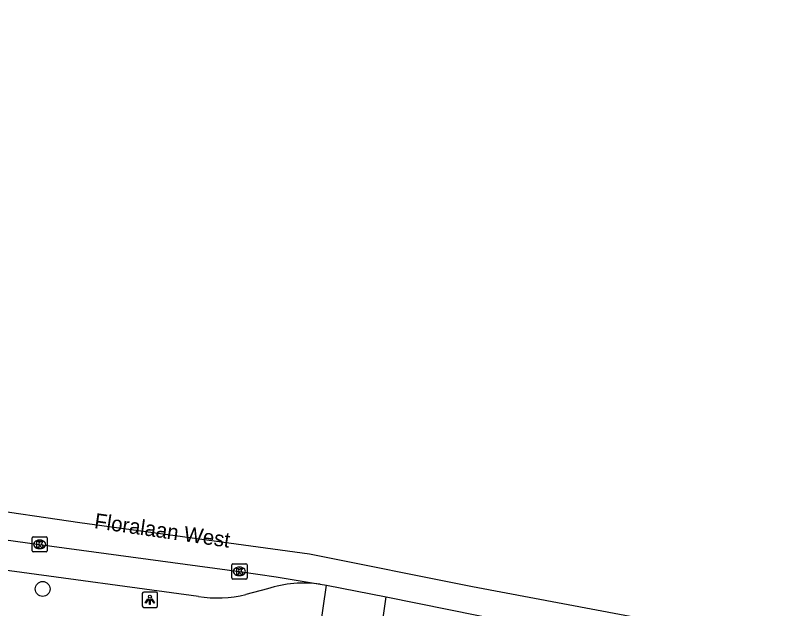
# Model space of a CAD drawing. Extents: x 161486 to 162249, y 379484 to 380829.
# Drawn here: x 162088.8 to 162140, y 380768.6 to 380807.6 of the extents above; entities that cross this region are included whole.
import ezdxf

# ---------------------------------------------------------------- set-up
doc = ezdxf.new("R2010")
doc.units = 0
for name, color, linetype in [('IMGEO_Boom', 7, 'Continuous'), ('IMGEO_Fietspad_open', 7, 'Continuous'), ('IMGEO_Kolk', 7, 'Continuous'), ('IMGEO_Lichtpunt', 7, 'Continuous'), ('IMGEO_Openbare_ruimte_label', 7, 'Continuous'), ('IMGEO_Rijbaan_lokaal_gesloten', 7, 'Continuous'), ('IMGEO_Voetpad_open', 7, 'Continuous')]:
    doc.layers.add(name, color=color, linetype=linetype)

msp = doc.modelspace()

# ---------------------------------------------------------------- linework, layer by layer
at = {"layer": 'IMGEO_Boom'}
msp.add_circle((162090.611, 380769.898), 0.489, dxfattribs=at)
at = {"layer": 'IMGEO_Fietspad_open'}
for points in [[(162082, 380773.982), (162090.414, 380772.833), (162103.563, 380771.053), (162105.995, 380770.702), (162108.893, 380770.206)], [(162108.893, 380770.206), (162109.295, 380770.138)], [(162109.295, 380770.138), (162113.227, 380769.38)], [(162113.227, 380769.38), (162121.37, 380767.728), (162122.685, 380767.488)]]:
    msp.add_lwpolyline(points, dxfattribs=at)
at = {"layer": 'IMGEO_Kolk'}
for p, q in [((162089.917, 380772.406), (162089.917, 380773.258)), ((162089.992, 380773.332), (162090.844, 380773.332)), ((162090.405, 380773.112), (162090.43, 380773.112)), ((162090.918, 380773.258), (162090.918, 380772.406)), ((162090.428, 380772.552), (162090.403, 380772.552)), ((162090.844, 380772.332), (162089.992, 380772.332)), ((162103.066, 380770.626), (162103.066, 380771.478)), ((162103.141, 380771.552), (162103.993, 380771.552)), ((162104.067, 380771.478), (162104.067, 380770.626)), ((162103.554, 380771.332), (162103.579, 380771.332)), ((162103.993, 380770.552), (162103.141, 380770.552)), ((162103.577, 380770.772), (162103.552, 380770.772))]:
    msp.add_line(p, q, dxfattribs=at)
for points in [[(162089.917, 380772.406), (162089.917, 380773.258)], [(162089.992, 380773.332), (162090.844, 380773.332)], [(162090.238, 380773.032), (162090.361, 380773.032), (162090.361, 380772.881), (162090.491, 380773.032), (162090.655, 380773.032), (162090.509, 380772.881), (162090.662, 380772.632), (162090.51, 380772.632), (162090.425, 380772.796), (162090.361, 380772.729), (162090.361, 380772.632), (162090.238, 380772.632), (162090.238, 380773.032)], [(162090.918, 380773.258), (162090.918, 380772.406)], [(162090.844, 380772.332), (162089.992, 380772.332)], [(162103.066, 380770.626), (162103.066, 380771.478)], [(162103.141, 380771.552), (162103.993, 380771.552)], [(162104.067, 380771.478), (162104.067, 380770.626)], [(162103.387, 380771.252), (162103.51, 380771.252), (162103.51, 380771.101), (162103.64, 380771.252), (162103.804, 380771.252), (162103.658, 380771.101), (162103.811, 380770.852), (162103.659, 380770.852), (162103.574, 380771.016), (162103.51, 380770.949), (162103.51, 380770.852), (162103.387, 380770.852), (162103.387, 380771.252)], [(162103.993, 380770.552), (162103.141, 380770.552)]]:
    msp.add_lwpolyline(points, dxfattribs=at)
for centre, start, end in [((162089.994, 380773.256), 91.552, 178.448), ((162089.994, 380773.256), 91.552, 178.448), ((162090.842, 380773.256), 1.552, 88.448), ((162090.842, 380773.256), 1.552, 88.448), ((162089.994, 380772.408), 181.552, 268.448), ((162089.994, 380772.408), 181.552, 268.448), ((162090.842, 380772.408), 271.552, 358.448), ((162090.842, 380772.408), 271.552, 358.448), ((162103.143, 380771.476), 91.552, 178.448), ((162103.143, 380771.476), 91.552, 178.448), ((162103.991, 380771.476), 1.552, 88.448), ((162103.991, 380771.476), 1.552, 88.448), ((162103.143, 380770.628), 181.552, 268.448), ((162103.143, 380770.628), 181.552, 268.448), ((162103.991, 380770.628), 271.552, 358.448), ((162103.991, 380770.628), 271.552, 358.448)]:
    msp.add_arc(centre, 0.0765, start, end, dxfattribs=at)
for centre, major_axis, ratio, start_param, end_param in [((162090.404, 380772.832), (-0.387, 0.002), 0.722429, 4.712389, 7.853982), ((162090.429, 380772.832), (-0.39, 0.002), 0.717154, 1.570796, 4.712389), ((162103.553, 380771.052), (-0.387, 0.002), 0.722429, 4.712389, 7.853982), ((162103.578, 380771.052), (-0.39, 0.002), 0.717154, 1.570796, 4.712389)]:
    msp.add_ellipse(centre, major_axis=major_axis, ratio=ratio, start_param=start_param, end_param=end_param, dxfattribs=at)
at = {"layer": 'IMGEO_Lichtpunt'}
for p, q in [((162097.174, 380769.588), (162097.174, 380768.781)), ((162097.174, 380769.588), (162097.174, 380768.781)), ((162098.076, 380769.683), (162097.268, 380769.683)), ((162098.076, 380769.683), (162097.268, 380769.683)), ((162098.17, 380768.781), (162098.17, 380769.588)), ((162098.17, 380768.781), (162098.17, 380769.588)), ((162097.268, 380768.687), (162098.076, 380768.687)), ((162097.268, 380768.687), (162098.076, 380768.687))]:
    msp.add_line(p, q, dxfattribs=at)
for points in [[(162097.548, 380769.252), (162097.587, 380769.224), (162097.399, 380768.962), (162097.361, 380768.989), (162097.548, 380769.252)], [(162097.65, 380769.204), (162097.697, 380769.204), (162097.697, 380768.882), (162097.65, 380768.882), (162097.65, 380769.204)], [(162097.76, 380769.224), (162097.798, 380769.251), (162097.985, 380768.989), (162097.946, 380768.961), (162097.76, 380769.224)]]:
    msp.add_lwpolyline(points, dxfattribs=at)
msp.add_circle((162097.673, 380769.386), 0.0994, dxfattribs=at)
for centre, start, end in [((162097.268, 380769.588), 90, 180), ((162097.268, 380769.588), 90, 180), ((162098.076, 380769.588), 0, 90), ((162098.076, 380769.588), 0, 90), ((162097.268, 380768.781), 180, 270), ((162097.268, 380768.781), 180, 270), ((162098.076, 380768.781), 270, 0), ((162098.076, 380768.781), 270, 360)]:
    msp.add_arc(centre, 0.0946, start, end, dxfattribs=at)
at = {"layer": 'IMGEO_Rijbaan_lokaal_gesloten'}
msp.add_lwpolyline([(161833.402, 380807.634), (161845.075, 380805.921), (161887.22, 380800.191), (161944.816, 380792.342), (162034.971, 380780.165), (162056.354, 380777.224), (162056.903, 380777.191), (162081.643, 380775.785), (162086.162, 380775.288), (162093.056, 380774.264), (162108.19, 380772.217), (162118.907, 380770.062), (162138.618, 380766.344), (162139.976, 380766.161)], dxfattribs=at)
at = {"layer": 'IMGEO_Voetpad_open'}
for points in [[(162100.863, 380769.405), (162087.955, 380771.156)], [(162108.45, 380764.256), (162109.295, 380770.138)], [(162105.425, 380769.902), (162103.996, 380769.532)], [(162112.411, 380763.701), (162113.227, 380769.38)]]:
    msp.add_lwpolyline(points, dxfattribs=at)
for centre, radius, start, end in [((162107.813, 380762.597), 7.685, 81.9185, 108.1008), ((162102.102, 380777.545), 8.234, 261.3445, 283.298)]:
    msp.add_arc(centre, radius, start, end, dxfattribs=at)

# ---------------------------------------------------------------- texts
at = {"layer": 'IMGEO_Openbare_ruimte_label'}
msp.add_text('Floralaan West', height=1, rotation=351.7241, dxfattribs=at).set_placement((162093.972, 380773.904))

doc.saveas('drawing.dxf')
